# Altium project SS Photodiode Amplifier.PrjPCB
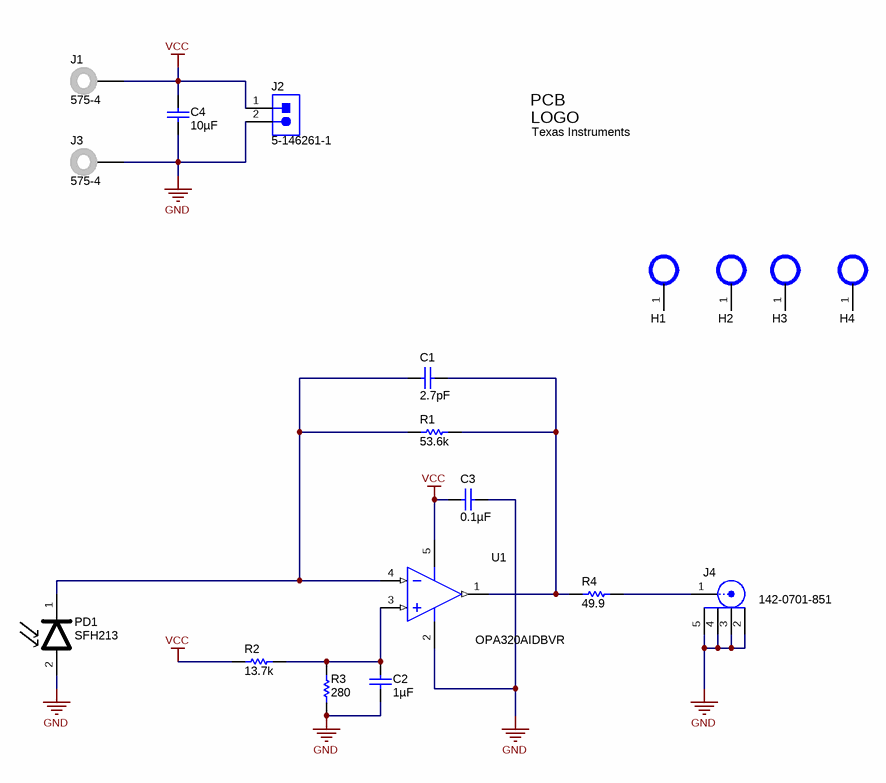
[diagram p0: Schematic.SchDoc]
CopyrightYear: 2012; PCB_Layout: Who did the Layout?; PCB_Rev: E1; PRJ_Customer: Public Release; PRJ_Engineer: Enter name of project lead; PRJ_Number: XX####; PRJ_Title: Change in menu Project|Project Options|Parameters; SCH_Rev: E1; TechSupport: http://www.ti.com/support
1 sheet, 19 parts. Net scope: global (net labels, ports and power ports of the same name join across sheets).
Board file: SS Photodiode Amplifier.PcbDoc

## Sheet Schematic.SchDoc: 1 MHz, Single Supply Photodiode Amplifier
size A4; Date: Not shown in title block; ApprovedBy: Not shown in title block; CheckedBy: Not shown in title block; Author: Not shown in title block; CompanyName: Not shown in title block; DrawnBy: Enter Full Name; Engineer: Not shown in title block; Organization: Not shown in title block; Address1: Not shown in title block; Address2: Not shown in title block; Address3: Not shown in title block; Address4: Not shown in title block; DocumentNumber: 2; Revision: Use project parameter SCH_Rev; SheetNumber: 2; SheetTotal: 3; PageSetup: Record=PageOptions|CenterHorizontal=True|CenterVertical=True|PrintScale=0.62|XCorrection=1.00|YCorrection=1.00|PrintKind=0|BorderSize=5000000|LeftOffset=0|BottomOffset=0|Orientation=2|PaperLength=1000|PaperWidth=1000|Scale=100|PaperSource=15|PrintQuality=600|MediaType=1|DitherType=10|PaperKind=Letter|PrintScaleMode=1

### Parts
C1  ValueDisplayed: 2.7pF  [0603]  (hidden comment: 06035A2R7CAT2A)
C2  ValueDisplayed: 1µF  [0603]  (hidden comment: C0603C105K4PACTU)
C3  ValueDisplayed: 0.1µF  [0603]  (hidden comment: 0603YC104JAT2A)
C4  ValueDisplayed: 10µF  [1210]  (hidden comment: C1210C106K8PACTU)
H1  NA  [Mounting Hole]  (value not drawn)  (no BOM)
H2  NA  [Mounting Hole]  (value not drawn)  (no BOM)
H3  NA  [Mounting Hole]  (value not drawn)  (no BOM)
H4  NA  [Mounting Hole]  (value not drawn)  (no BOM)
J1  575-4  [Keystone_575-4]
J2  5-146261-1  [CONN_5-146261-1]
J3  575-4  [Keystone_575-4]
J4  142-0701-851  [Emerson_142-0701-851]
Logo1  Texas Instruments  [TI_Stacked_Overlay_Small]  (no BOM)
PD1  SFH213  [PDB-C156]
R1  value 53.6k  [0603]  (hidden comment: CRCW060353K6FKEA)
R2  value 13.7k  [0603]  (hidden comment: CRCW060313K7FKEA)
R3  value 280  [0603]  (hidden comment: CRCW0603280RFKEA)
R4  value 49.9  [0603]  (hidden comment: CRCW060349R9FKEA)
U1  OPA320AIDBVR  [DBV0005A_N]

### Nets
GND: C2.2 C3.1 C4.2 J2.2 J3.1 J4.2 J4.3 J4.4 J4.5 PD1.2(A) R3.1 U1.2(V-)
VCC: C3.2 C4.1 J1.1 J2.1 R2.1 U1.5(V+)
NetC1_1: C1.1 R1.2 R4.1 U1.1(OUT)
NetC1_2: C1.2 PD1.1(C) R1.1 U1.4(IN-)
NetC2_1: C2.1 R2.2 R3.2 U1.3(IN+)
NetJ4_1: J4.1 R4.2

Not connected (* = marked no-connect by the designer): H1 1; H2 1; H3 1; H4 1

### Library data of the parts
C1 = 06035A2R7CAT2A: CAP, CERM, 2.7pF, 50V, +/-9%, C0G/NP0, 0603; Manufacturer: AVX; Polarized: N; CompType: Capacitor; U/M: EA; Cap_F: 0.0000000000027; Tolerance_%: 9; ESR_Ohm: 0.902; Value1: 0.902 ohm; VDC_V: 50; TaMin_C: -55; TaMax_C: 125
C2 = C0603C105K4PACTU: CAP, CERM, 1uF, 16V, +/-10%, X5R, 0603; Manufacturer: Kemet; Polarized: N; CompType: Capacitor; U/M: EA; Cap_F: 0.000001; Tolerance_%: 10; Value1: Unknown; VDC_V: 16; TaMin_C: -55; TaMax_C: 85
C3 = 0603YC104JAT2A: CAP, CERM, 0.1uF, 16V, +/-5%, X7R, 0603; Manufacturer: AVX; Polarized: N; CompType: Capacitor; U/M: EA; Cap_F: 0.0000001; Tolerance_%: 5; ESR_Ohm: 0.039; Value1: 0.039 ohm; VDC_V: 16; TaMin_C: -55; TaMax_C: 125
C4 = C1210C106K8PACTU: CAP, CERM, 10uF, 10V, +/-10%, X5R, 1210; Manufacturer: Kemet; Polarized: N; CompType: Capacitor; U/M: EA; Cap_F: 0.00001; Tolerance_%: 10; ESR_Ohm: 0.008; Value1: 0.008 ohm; IRMS_A: 6.9; TaMin_C: -55; TaMax_C: 85
H1-H4 = Mounting Hole: Manufacturer: Used in BOM report; SymbolVersion: use current date i.e. 2008-05-20; SymbolCreator: Use LDAP id; CompType: Used in some BOM reports.  Useful for finding later.; U/M: EA, IN, or GM
J1 J3 = 575-4: Standard Banana Jack, Uninsulated, 5.5mm; Manufacturer: Keystone; CompType: Connector; U/M: EA
J2 = 5-146261-1: Header, 100mil, 2x1, Gold, TH; Manufacturer: TE Connectivity; SymbolCreator: a0412235; U/M: EA
J4 = 142-0701-851: Connector, SMT, End launch SMA 50 ohm; Manufacturer: Emerson Network Power; Alternate Manufacturer: Any; Alternate PartNumber: Equivalent; U/M: EA
Logo1 = TI_Logo: Texas Instrument Corporate Signature; SymbolCreator: codlsc
PD1 = SFH-213: Manufacturer: Osram; SymbolVersion: use current date i.e. 2008-05-20; SymbolCreator: Use LDAP id; CompType: Used in some BOM reports.  Useful for finding later.; U/M: EA, IN, or GM
R1 = CRCW060353K6FKEA: RES, 53.6k ohm, 1%, 0.1W, 0603; Manufacturer: Vishay-Dale; CompType: Resistor; Res_ohm: 53600; Value_Code: 53k6; Tolerance_%: 1; Power_W: 0.1; VDC_V: 75; TempCo: 100 ppm/C; EIA_Code: E96; U/M: EA
R2 = CRCW060313K7FKEA: RES, 13.7k ohm, 1%, 0.1W, 0603; Manufacturer: Vishay-Dale; CompType: Resistor; Res_ohm: 13700; Value_Code: 13k7; Tolerance_%: 1; Power_W: 0.1; VDC_V: 75; TempCo: 100 ppm/C; EIA_Code: E96; U/M: EA
R3 = CRCW0603280RFKEA: RES, 280 ohm, 1%, 0.1W, 0603; Manufacturer: Vishay-Dale; CompType: Resistor; Value_Code: 280R; Tolerance_%: 1; Power_W: 0.1; VDC_V: 75; TempCo: 100 ppm/C; EIA_Code: E96; U/M: EA
R4 = CRCW060349R9FKEA: RES, 49.9 ohm, 1%, 0.1W, 0603; Manufacturer: Vishay-Dale; CompType: Resistor; Value_Code: 49R9; Tolerance_%: 1; Power_W: 0.1; VDC_V: 75; TempCo: 100 ppm/C; EIA_Code: E96; U/M: EA
U1 = OPA320AIDBVR: Precision, 20 MHz, 0.9 pA Ib, RRIO, CMOS Operational Amplifier, 1.8 to 5.5 V, -40 to 125 degC, 5-pin SOT23 (DBV0005A), Green (RoHS & no Sb/Br); Manufacturer: Texas Instruments; Alternate Manufacturer: None; Alternate PartNumber: Equivalent; CMRR(Min)(dB): 100; IIB(Max)(pA): 0.9; Iq per channel(Max)(mA): 1.75; Number of Channels: 2; Offset Drift(Typ)(uV/C): 1.5; Slew Rate(Typ)(V/us): 10; Sub Family: High Output Current Amplifier (>=50mA), Low Input Bias Current Amp (<=10pA), Low Noise Amp (<=10nV/rtHz), Low Offset Voltage Amplifier (<=500uV), Low Supply Voltage Amplifier (<=2.7V), Precision Amplifier; Total Supply Voltage(Max)(+5V is 5, +/-5V is 10): 5.5; Total Supply Voltage(Min)(+5V is 5, +/-5V is 10): 1.8; Vio (25C)(Max)(mV): 0.15; Vn at 1kHz(Typ)(nV/rtHz): 8.5

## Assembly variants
001: all parts fitted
